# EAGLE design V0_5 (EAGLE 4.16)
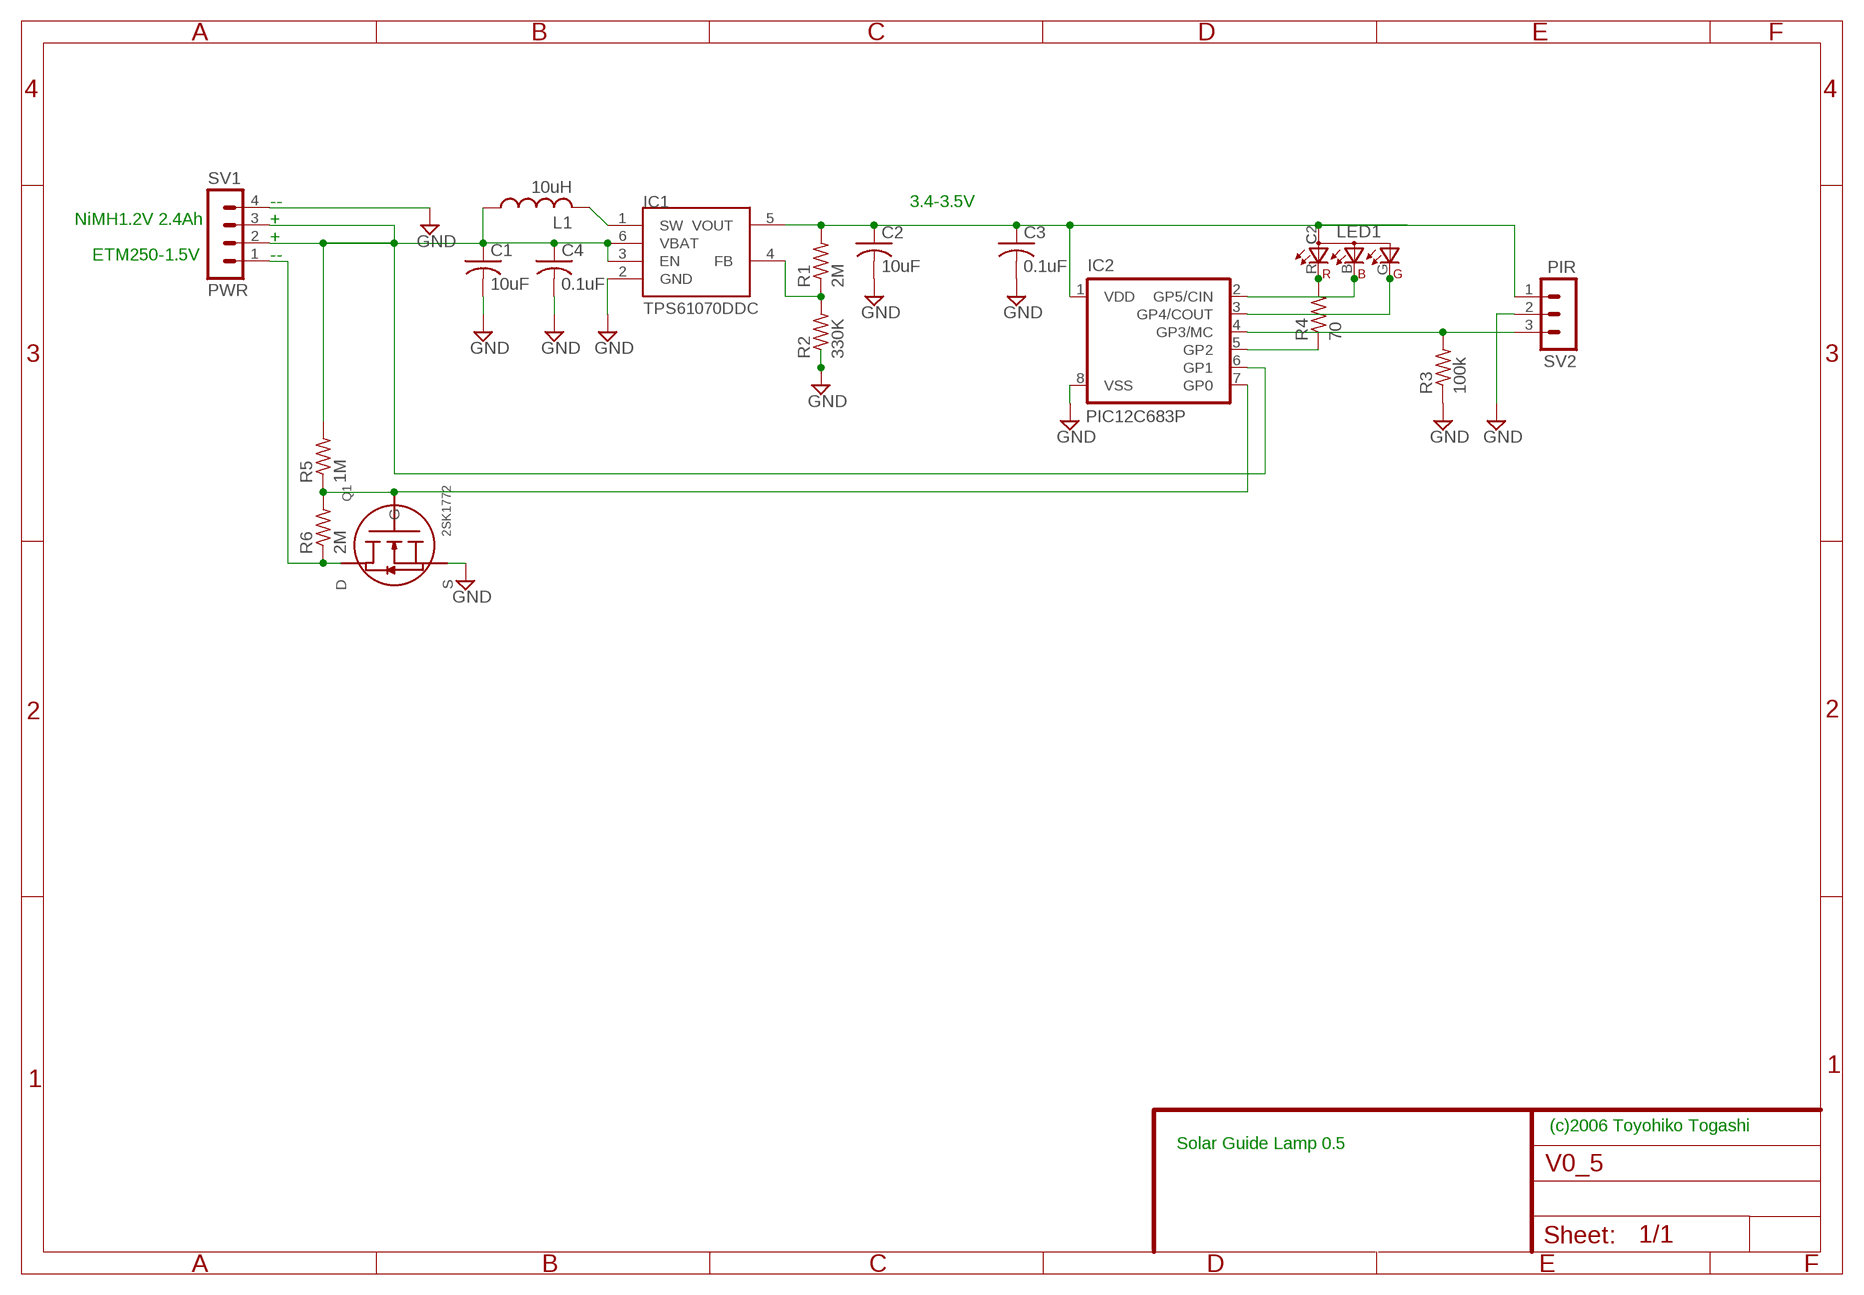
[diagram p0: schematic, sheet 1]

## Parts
C1  10uF  C-USC2012  [C2012]
C2  10uF  C-USC2012  [C2012]
C3  0.1uF  C-USC2012  [C2012]
C4  0.1uF  C-USC2012  [C2012]
IC1  TPS61070DDC  [SOT23-6L]
IC2  PIC12C683P  [DIL8]
L1  10uH  L-USL5650M  [L5650M]
LED1  EP204K-35G1R1B1-CA  [EP204K]
Q1  2SK1772  [UPAK-RENESAS]
R1  2M  R-US_M2012  [M2012]
R2  330K  R-US_M2012  [M2012]
R3  100k  R-US_M2012  [M2012]
R4  70  R-US_M2012  [M2012]
R5  1M  R-US_M2012  [M2012]
R6  2M  R-US_M2012  [M2012]
SV1  PWR  MA04-1  [MA04-1]
SV2  PIR  MA03-1  [MA03-1]

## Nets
GND: C1.2 C2.2 C3.2 C4.2 IC1.2(GND) IC2.8(VSS) Q1.3(S) R2.1 R3.1 SV1.4 SV2.2
LED1: C2.1 C3.1 IC1.5(VOUT) IC2.1(VDD) LED1.C2(A1) LED1.C(A2) R1.2 SV2.1
N$1: IC2.5(GP2) R4.1
N$2: IC1.1(SW) L1.2
N$3: IC2.3(GP4/COUT) LED1.G(CGREEN)
N$4: C1.1 C4.1 IC1.3(EN) IC1.6(VBAT) IC2.6(GP1) L1.1 R5.2 SV1.2 SV1.3
N$5: IC2.2(GP5/CIN) LED1.B(CBLUE)
N$6: LED1.R(CRED) R4.2
N$7: Q1.2(D) R6.1 SV1.1
N$9: IC2.4(GP3/MC) R3.2 SV2.3
N$11: IC2.7(GP0) Q1.1(G) R5.1 R6.2
N$12: IC1.4(FB) R1.1 R2.2

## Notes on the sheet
- -- | 3.4-3.5V
- NiMH1.2V 2.4Ah | +
- +
- ETM250-1.5V | --
- (c)2006 Toyohiko Togashi
- Solar Guide Lamp 0.5

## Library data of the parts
C1-C4 = rcl:C-US: CAPACITOR, American symbol
IC1 = TOG:TPS61070DDC: Step-up SWITCHING REGULATOR
IC2 = microchip:PIC12C*?: MICROCONTROLLER
L1 = rcl:L-US: INDUCTOR, American symbol
LED1 = led:EP204K-35G1R1B1-CA
Q1 = TOG:2SK1772
R1-R6 = rcl:R-US_: RESISTOR, American symbol
SV1 = con-lstb:MA04-1: PIN HEADER
SV2 = con-lstb:MA03-1: PIN HEADER

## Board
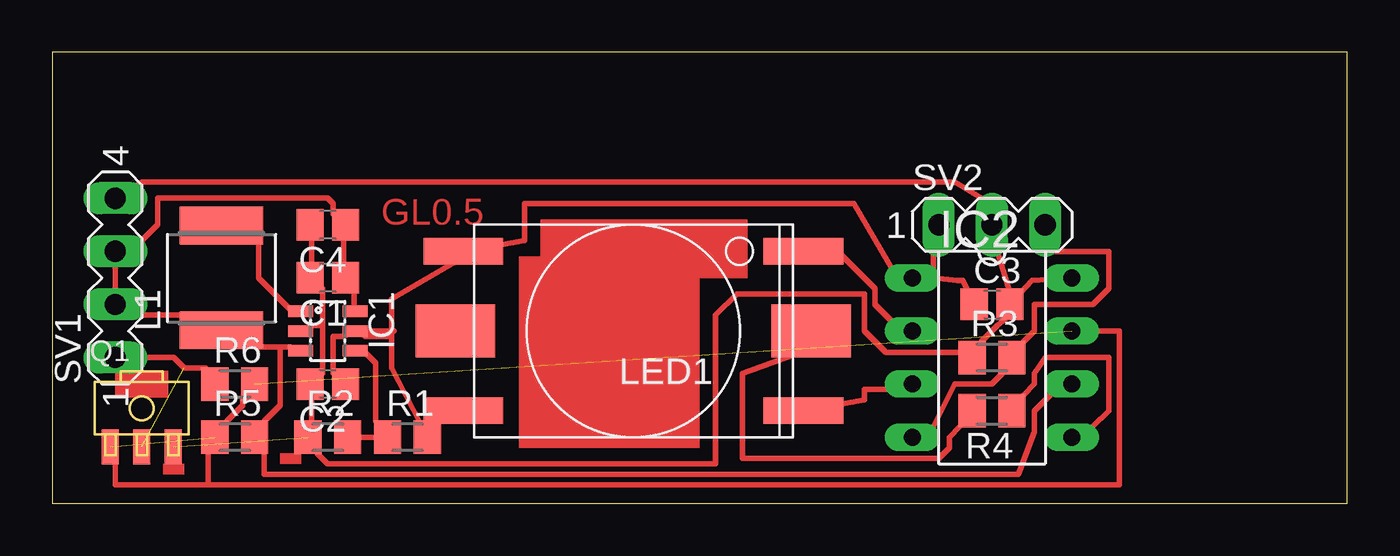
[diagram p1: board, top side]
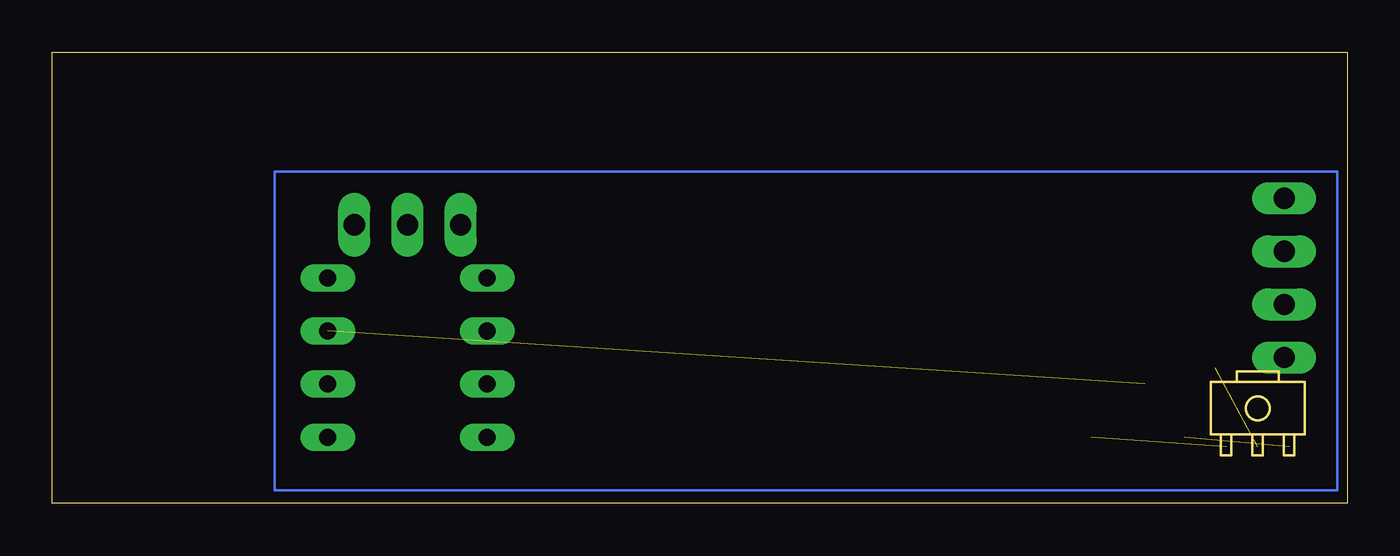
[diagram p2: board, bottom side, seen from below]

Size 61.9 x 21.58 mm. Coordinates in mm from the lower left corner, seen from the top.
Outline: 0,0 61.9,0 61.9,21.58 0,21.58 0,0
Copper layers (1*16): Top 0.035mm / dielectric 1.5mm / Bottom 0.035mm
Design rules "default": minimum track width 10mil, minimum drill 24mil, track to track 8mil, track to pad 8mil, pad to pad 8mil, via to via 8mil, smd to smd 8mil, copper to edge 40mil, drill to drill 8mil, minimum pad ring 10mil, minimum via ring 8mil, stop-mask expansion 4mil, vias tented up to drill 0mil, thermal gap 10mil

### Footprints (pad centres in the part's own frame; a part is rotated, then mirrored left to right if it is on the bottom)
C2012 = smd 1.3 x 1.5: 1 -0.85,0; 2 0.85,0
SOT23-6L = smd 0.55 x 1.2: 1 -0.95,-1.3; 2 0,-1.3; 3 0.95,-1.3; 4 0.95,1.3; 5 0,1.3; 6 -0.95,1.3
DIL8 = drill 0.813 long: 1 -3.81,-3.81; 2 -1.27,-3.81; 3 1.27,-3.81; 4 3.81,-3.81; 5 3.81,3.81; 6 1.27,3.81; 7 -1.27,3.81; 8 -3.81,3.81
L5650M = smd 1.8 x 4: 1 -2.5,0; 2 2.5,0
EP204K = smd 1.27 x 3.81: B 3.81,-8.128; C -3.81,8.128; C2 3.81,8.128; G -3.81,-8.128 | smd 2.54 x 3.81: R 0,-8.509; R2 0,8.509
UPAK-RENESAS = smd 0.813 x 1.676: 1 -1.5,-1.1; 2 0,-1.1; 3 1.5,-1.1
M2012 = smd 1.3 x 1.6: 1 -0.95,0; 2 0.95,0
MA04-1 = drill 1.016 long: 1 -3.81,0; 2 -1.27,0; 3 1.27,0; 4 3.81,0
MA03-1 = drill 1.016 long: 1 -2.54,0; 2 0,0; 3 2.54,0

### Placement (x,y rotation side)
C1  13.17,10.79 180 top
C2  13.17,5.71 180 top
C3  44.92,9.52 0 top
C4  13.17,13.33 180 top
IC1  13.17,8.25 270 top
IC2  44.92,6.98 270 top
L1  8.09,10.79 90 top
LED1  27.77,8.25 90 top
Q1  4.28,3.8 0 top
R1  16.98,3.17 0 top
R2  13.17,3.17 0 top
R3  44.92,6.98 0 top
R4  44.92,4.44 180 top
R5  8.73,3.17 0 top
R6  8.73,5.71 0 top
SV1  3.01,10.79 90 top
SV2  44.92,13.33 0 top

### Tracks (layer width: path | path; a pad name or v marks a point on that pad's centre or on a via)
GND  (1 unrouted)
  Top 0.254: 12.92,8.5 12.41,8.5 IC1.2 | 12.92,8.5 12.92,10.28 C1.2 12.41,11.3 12.41,12.82 C4.2 | 12.92,8.5 12.92,6.22 C2.2 12.41,5.2 12.41,3.93 R2.1 12.66,2.41 13.17,1.9 31.71,1.9 31.71,9.01 32.73,10.03 38.82,10.03 38.82,8.25 39.84,7.23 43.4,7.23 R3.1 44.41,7.74 45.17,8.5 45.81,9.01 C3.2 | C3.2 46.82,10.66 IC2.8 | C3.2 45.81,10.03 45.17,12.06 SV2.2 44.41,14.6 43.14,15.36 4.28,15.36 SV1.4
LED1
  Top 0.254: 40.86,10.92 43.27,10.66 43.52,10.66 C3.1 | SV2.1 42.13,12.06 42.13,11.3 IC2.1 40.86,10.92 | C2.1 13.42,6.22 13.42,8 13.93,8 IC1.5 14.95,8 16.22,8 | LED1.C 19.27,3.93 18.5,3.93 R1.2 16.22,6.47 16.22,8 | 16.22,8 16.22,9.77 19.27,11.55 LED1.C2 22.57,12.57 22.57,14.35 38.32,14.35 40.09,11.3 40.86,10.92
N$1
  Top 0.254: R4.1 46.44,5.2 46.95,5.71 46.95,6.22 47.46,6.98 50.51,6.98 50.51,4.44 49.75,3.68 IC2.5
N$2
  Top 0.254: IC1.1 11.39,9.27 9.87,10.79 9.87,12.57 L1.2
N$3
  Top 0.254: IC2.3 39.84,5.46 38.82,5.46 38.82,4.95 LED1.G
N$4
  Top 0.254: IC1.6 14.44,9.27 14.44,10.28 C1.1 13.93,11.3 13.93,12.82 C4.1 13.42,13.84 13.42,14.35 13.17,14.6 5.04,14.6 5.04,13.33 4.28,12.57 SV1.3 SV1.2 4.28,9.01 6.31,9.01 L1.1 9.87,7.49 10.88,7.49 | 10.88,7.49 11.39,7.49 IC1.3 | 10.88,7.49 10.88,4.69 10.12,3.93 R5.2 10.12,2.41 10.12,1.39 46.19,1.39 46.95,3.42 46.95,4.44 47.71,5.2 IC2.6
N$5
  Top 0.254: IC2.2 40.09,8.76 39.33,9.52 39.33,10.28 37.55,12.06 LED1.B
N$6
  Top 0.254: R4.2 43.4,3.68 42.89,3.17 42.89,2.66 42.38,2.15 32.98,2.15 32.98,6.22 35.78,7.23 LED1.R
N$7  (1 unrouted)
  Top 0.254: R6.1 7.33,6.47 6.31,6.47 5.8,6.98 SV1.1
N$8
  Bottom 0.127: 0.47,0.63 51.27,0.63 51.27,15.87 0.47,15.87 0.47,0.63
N$9
  Top 0.254: IC2.4 42.13,3.68 43.14,5.71 44.92,5.71 45.43,6.22 R3.2 46.44,7.74 46.95,8.25 46.95,9.52 49.75,9.52 50.51,10.28 50.51,12.06 47.97,12.06 SV2.3
N$10
  Top 0.254: 14.44,8.25 16.34,8.25
N$11  (2 unrouted)
  Top 0.254: R5.1 8.34,3.93 9.11,4.69 9.11,4.95 R6.2
N$12
  Top 0.254: IC1.4 14.95,7.23 15.46,6.73 15.46,3.93 R1.1 R2.2
N$13
  Top 0.254: 3.01,2.54 3.01,0.88 7.46,0.88 | 7.46,2.54 7.46,0.88 | 7.46,0.88 51.02,0.88 51.02,8.25 49.37,8.25
(copper drawn outside any net)
  shapes: Top area x5

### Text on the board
Top: GL0.5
